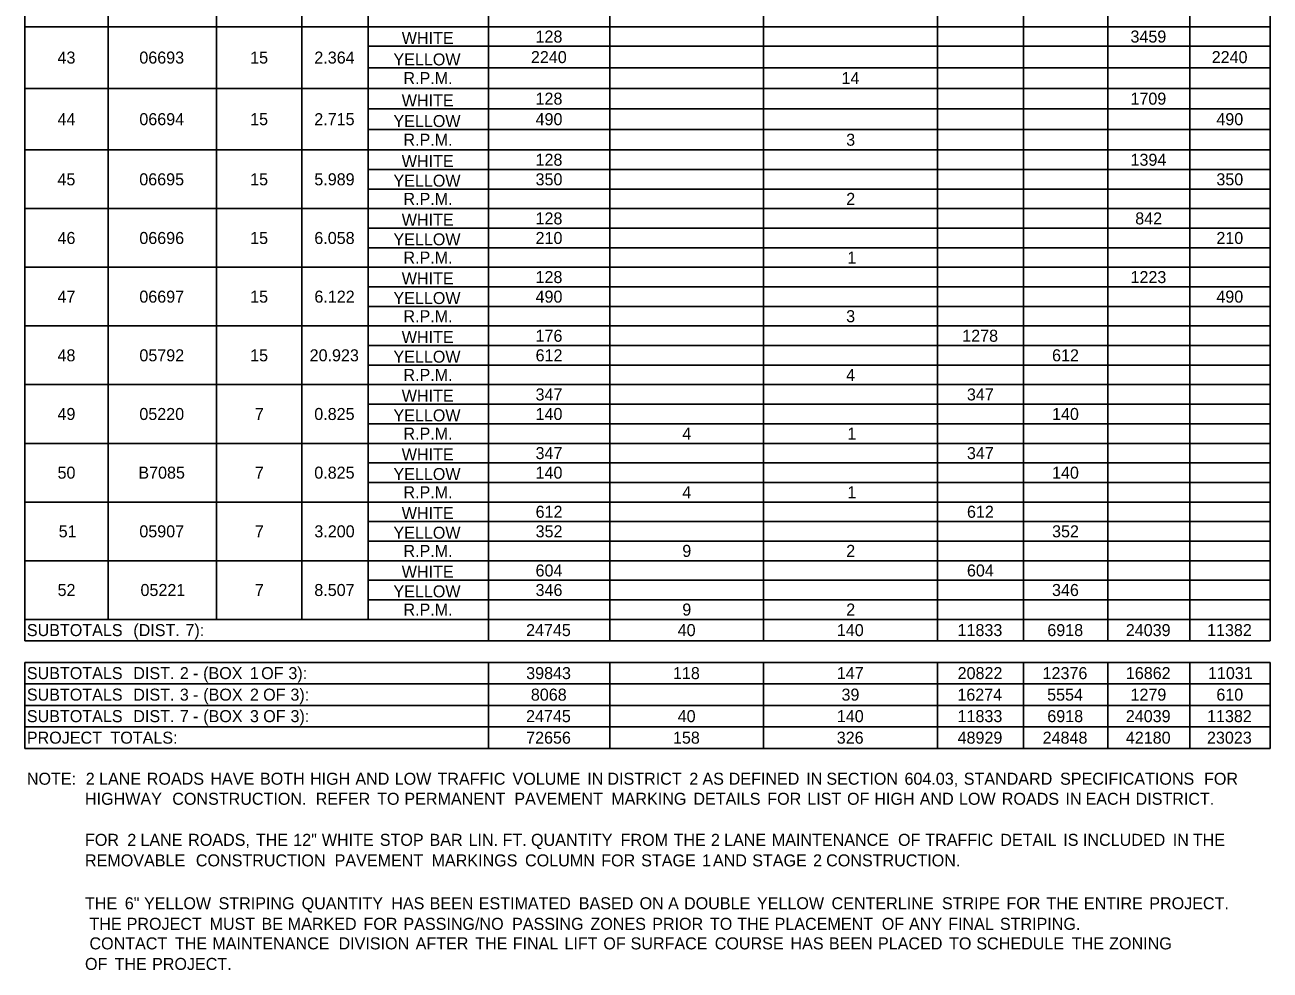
# Model space of a CAD drawing. Extents: x 544250 to 1930787, y -1948365 to 596640.
# Drawn here: x 551931 to 552552, y -1948306 to -1947835 of the extents above; entities that cross this region are included whole.
import ezdxf

# ---------------------------------------------------------------- set-up
doc = ezdxf.new("R2010")
doc.units = 0
doc.layers.add('Default', color=7, linetype='Continuous')

msp = doc.modelspace()

# ---------------------------------------------------------------- linework, layer by layer
at = {"layer": 'Default'}
for p, q in [((551930.97, -1948141.95), (551930.97, -1947372.68)), ((551972.4, -1948131.23), (551972.4, -1947372.68)), ((552026.52, -1948131.23), (552026.52, -1947372.68)), ((552068.93, -1948131.23), (552068.93, -1947372.68)), ((552102.08, -1948131.23), (552102.08, -1947372.68)), ((552162.04, -1948141.95), (552162.04, -1947372.68)), ((552385.8, -1948141.95), (552385.8, -1947372.68)), ((552470.63, -1948141.95), (552470.63, -1947372.68)), ((552551.55, -1948141.95), (552551.55, -1947372.68)), ((552026.52, -1948131.23), (552026.52, -1947440.93)), ((552068.93, -1948131.23), (552068.93, -1947440.93)), ((552222.49, -1948141.95), (552222.49, -1947440.93)), ((552299.03, -1948141.95), (552299.03, -1947440.93)), ((552428.7, -1948141.95), (552428.7, -1947440.93)), ((552511.58, -1948141.95), (552511.58, -1947440.93)), ((552470.63, -1947845.55), (552470.63, -1947826.05)), ((551930.97, -1947835.8), (552551.55, -1947835.8)), ((552162.04, -1947856.28), (552162.04, -1947835.8)), ((552385.8, -1947856.28), (552385.8, -1947835.8)), ((552102.08, -1947845.55), (552551.55, -1947845.55)), ((552511.58, -1947856.28), (552511.58, -1947845.55)), ((552102.08, -1947856.28), (552162.04, -1947856.28)), ((552102.08, -1947856.28), (552551.55, -1947856.28)), ((552470.63, -1947876.75), (552470.63, -1947856.28)), ((551930.97, -1947866.52), (552551.55, -1947866.52)), ((552162.04, -1947886.99), (552162.04, -1947866.52)), ((552385.8, -1947886.99), (552385.8, -1947866.52)), ((552102.08, -1947876.75), (552551.55, -1947876.75)), ((552511.58, -1947886.99), (552511.58, -1947876.75)), ((552102.08, -1947886.99), (552162.04, -1947886.99)), ((552102.08, -1947886.99), (552551.55, -1947886.99)), ((552470.63, -1947906.98), (552470.63, -1947886.99)), ((551930.97, -1947897.23), (552551.55, -1947897.23)), ((552162.04, -1947916.73), (552162.04, -1947897.23)), ((552385.8, -1947916.73), (552385.8, -1947897.23)), ((552102.08, -1947906.98), (552551.55, -1947906.98)), ((552511.58, -1947916.73), (552511.58, -1947906.98)), ((552102.08, -1947916.73), (552162.04, -1947916.73)), ((552102.08, -1947916.73), (552551.55, -1947916.73)), ((552470.63, -1947936.23), (552470.63, -1947916.73)), ((551930.97, -1947926.48), (552551.55, -1947926.48)), ((552162.04, -1947945.98), (552162.04, -1947926.48)), ((552385.8, -1947945.98), (552385.8, -1947926.48)), ((552102.08, -1947936.23), (552551.55, -1947936.23)), ((552511.58, -1947945.98), (552511.58, -1947936.23)), ((552102.08, -1947945.98), (552162.04, -1947945.98)), ((552102.08, -1947945.98), (552551.55, -1947945.98)), ((552470.63, -1947965.48), (552470.63, -1947945.98)), ((551930.97, -1947955.73), (552551.55, -1947955.73)), ((552162.04, -1947975.23), (552162.04, -1947955.73)), ((552385.8, -1947975.23), (552385.8, -1947955.73)), ((552102.08, -1947965.48), (552551.55, -1947965.48)), ((552511.58, -1947975.23), (552511.58, -1947965.48)), ((552102.08, -1947975.23), (552162.04, -1947975.23)), ((552102.08, -1947975.23), (552551.55, -1947975.23)), ((552470.63, -1947994.73), (552470.63, -1947975.23)), ((551930.97, -1947984.98), (552551.55, -1947984.98)), ((552102.08, -1947984.98), (552162.04, -1947984.98)), ((552102.08, -1948131.23), (552102.08, -1947984.98)), ((552162.04, -1948004.48), (552162.04, -1947984.98)), ((552385.8, -1948004.48), (552385.8, -1947984.98)), ((552102.08, -1947994.73), (552551.55, -1947994.73)), ((552511.58, -1948004.48), (552511.58, -1947994.73)), ((552102.08, -1948004.48), (552551.55, -1948004.48)), ((552470.63, -1948023.98), (552470.63, -1948004.48)), ((551930.97, -1948014.23), (552551.55, -1948014.23)), ((552102.08, -1948014.23), (552162.04, -1948014.23)), ((552162.04, -1948033.73), (552162.04, -1948014.23)), ((552385.8, -1948033.73), (552385.8, -1948014.23)), ((552102.08, -1948023.98), (552551.55, -1948023.98)), ((552511.58, -1948033.73), (552511.58, -1948023.98)), ((552102.08, -1948033.73), (552551.55, -1948033.73)), ((552470.63, -1948053.23), (552470.63, -1948033.73)), ((551930.97, -1948043.48), (552551.55, -1948043.48)), ((552102.08, -1948043.48), (552162.04, -1948043.48)), ((552162.04, -1948062.98), (552162.04, -1948043.48)), ((552385.8, -1948062.98), (552385.8, -1948043.48)), ((552102.08, -1948053.23), (552551.55, -1948053.23)), ((552511.58, -1948062.98), (552511.58, -1948053.23)), ((552102.08, -1948062.98), (552551.55, -1948062.98)), ((552470.63, -1948082.48), (552470.63, -1948062.98)), ((551930.97, -1948072.73), (552551.55, -1948072.73)), ((552102.08, -1948072.73), (552162.04, -1948072.73)), ((552162.04, -1948092.23), (552162.04, -1948072.73)), ((552385.8, -1948092.23), (552385.8, -1948072.73)), ((552102.08, -1948082.48), (552551.55, -1948082.48)), ((552511.58, -1948092.23), (552511.58, -1948082.48)), ((552102.08, -1948092.23), (552551.55, -1948092.23)), ((552470.63, -1948111.73), (552470.63, -1948092.23)), ((551930.97, -1948101.98), (552551.55, -1948101.98)), ((552102.08, -1948101.98), (552551.55, -1948101.98)), ((552162.04, -1948121.48), (552162.04, -1948101.98)), ((552385.8, -1948121.48), (552385.8, -1948101.98)), ((552102.08, -1948111.73), (552551.55, -1948111.73)), ((552511.58, -1948121.48), (552511.58, -1948111.73)), ((552102.08, -1948121.48), (552551.55, -1948121.48)), ((552470.63, -1948141.95), (552470.63, -1948121.48)), ((551930.97, -1948131.23), (552551.55, -1948131.23)), ((552162.04, -1948141.95), (552162.04, -1948131.23)), ((552222.49, -1948141.95), (552222.49, -1948131.23)), ((552299.03, -1948141.95), (552299.03, -1948131.23)), ((552385.8, -1948141.95), (552385.8, -1948131.23)), ((552428.7, -1948141.95), (552428.7, -1948131.23)), ((552511.58, -1948141.95), (552511.58, -1948131.23)), ((551930.97, -1948141.95), (552551.55, -1948141.95)), ((551930.97, -1948152.68), (552551.55, -1948152.68)), ((551930.97, -1948152.68), (552551.55, -1948152.68)), ((551930.97, -1948195.58), (551930.97, -1948152.68)), ((552162.04, -1948195.58), (552162.04, -1948152.68)), ((552162.04, -1948195.58), (552162.04, -1948152.68)), ((552222.49, -1948195.58), (552222.49, -1948152.68)), ((552299.03, -1948195.58), (552299.03, -1948152.68)), ((552385.8, -1948195.58), (552385.8, -1948152.68)), ((552428.7, -1948195.58), (552428.7, -1948152.68)), ((552470.63, -1948195.58), (552470.63, -1948152.68)), ((552511.58, -1948195.58), (552511.58, -1948152.68)), ((552551.55, -1948195.58), (552551.55, -1948152.68)), ((551930.97, -1948163.4), (552551.55, -1948163.4)), ((551930.97, -1948174.13), (552551.55, -1948174.13)), ((551930.97, -1948184.85), (552551.55, -1948184.85)), ((551930.97, -1948195.58), (552551.55, -1948195.58))]:
    msp.add_line(p, q, dxfattribs=at)

# ---------------------------------------------------------------- texts
for s, p in [('128', (552185.46, -1947843.68)), ('3459', (552481.97, -1947843.68)), ('WHITE', (552118.78, -1947844.35)), ('43', (551947.22, -1947854.16)), ('06693', (551988, -1947854.16)), ('15', (552043.23, -1947854.16)), ('2.364', (552075.22, -1947854.16)), ('YELLOW', (552114.64, -1947855.08)), ('2240', (552183.15, -1947853.92)), ('2240', (552522.45, -1947853.92)), ('R.P.M.', (552119.62, -1947864.4)), ('14', (552337.96, -1947864.4)), ('128', (552185.46, -1947874.64)), ('1709', (552481.97, -1947874.64)), ('WHITE', (552118.78, -1947875.55)), ('44', (551947.23, -1947884.87)), ('06694', (551988.01, -1947884.87)), ('15', (552043.23, -1947884.87)), ('2.715', (552075.19, -1947884.87)), ('YELLOW', (552114.64, -1947885.79)), ('490', (552185.48, -1947884.87)), ('490', (552524.78, -1947884.87)), ('R.P.M.', (552119.62, -1947895.11)), ('3', (552340.28, -1947895.11)), ('WHITE', (552118.78, -1947905.78)), ('128', (552185.46, -1947905.1)), ('1394', (552481.99, -1947905.1)), ('45', (551947.19, -1947914.85)), ('06695', (551987.98, -1947914.85)), ('15', (552043.23, -1947914.85)), ('5.989', (552075.21, -1947914.85)), ('YELLOW', (552114.64, -1947915.53)), ('350', (552185.48, -1947914.85)), ('350', (552524.78, -1947914.85)), ('R.P.M.', (552119.62, -1947924.6)), ('2', (552340.31, -1947924.6)), ('WHITE', (552118.78, -1947935.03)), ('128', (552185.46, -1947934.35)), ('842', (552484.34, -1947934.35)), ('46', (551947.22, -1947944.1)), ('06696', (551988, -1947944.1)), ('15', (552043.23, -1947944.1)), ('6.058', (552075.21, -1947944.1)), ('YELLOW', (552114.64, -1947944.78)), ('210', (552185.48, -1947944.1)), ('210', (552524.78, -1947944.1)), ('R.P.M.', (552119.62, -1947953.85)), ('1', (552340.86, -1947953.85)), ('WHITE', (552118.78, -1947964.28)), ('128', (552185.46, -1947963.6)), ('1223', (552481.97, -1947963.6)), ('47', (551947.22, -1947973.35)), ('06697', (551988, -1947973.35)), ('15', (552043.23, -1947973.35)), ('6.122', (552075.24, -1947973.35)), ('YELLOW', (552114.64, -1947974.03)), ('490', (552185.48, -1947973.35)), ('490', (552524.78, -1947973.35)), ('R.P.M.', (552119.62, -1947983.1)), ('3', (552340.28, -1947983.1)), ('176', (552185.47, -1947992.85)), ('1278', (552398.12, -1947992.85)), ('WHITE', (552118.78, -1947993.53)), ('48', (551947.21, -1948002.6)), ('05792', (551988.03, -1948002.6)), ('15', (552043.23, -1948002.6)), ('20.923', (552072.88, -1948002.6)), ('YELLOW', (552114.64, -1948003.28)), ('612', (552185.5, -1948002.6)), ('612', (552442.9, -1948002.6)), ('R.P.M.', (552119.62, -1948012.35)), ('4', (552340.29, -1948012.35)), ('WHITE', (552118.78, -1948022.78)), ('347', (552185.47, -1948022.1)), ('347', (552400.45, -1948022.1)), ('49', (551947.21, -1948031.85)), ('05220', (551988.01, -1948031.85)), ('7', (552045.58, -1948031.85)), ('0.825', (552075.19, -1948031.85)), ('YELLOW', (552114.64, -1948032.53)), ('140', (552185.48, -1948031.85)), ('140', (552442.88, -1948031.85)), ('R.P.M.', (552119.62, -1948041.6)), ('4', (552258.63, -1948041.6)), ('1', (552340.86, -1948041.6)), ('WHITE', (552118.78, -1948052.03)), ('347', (552185.47, -1948051.35)), ('347', (552400.45, -1948051.35)), ('50', (551947.23, -1948061.1)), ('B7085', (551987.51, -1948061.1)), ('7', (552045.58, -1948061.1)), ('0.825', (552075.19, -1948061.1)), ('140', (552185.48, -1948061.1)), ('140', (552442.88, -1948061.1)), ('YELLOW', (552114.64, -1948061.78)), ('R.P.M.', (552119.62, -1948070.85)), ('4', (552258.63, -1948070.85)), ('1', (552340.86, -1948070.85)), ('WHITE', (552118.78, -1948081.28)), ('612', (552185.5, -1948080.6)), ('612', (552400.49, -1948080.6)), ('51', (551947.8, -1948090.35)), ('05907', (551988, -1948090.35)), ('7', (552045.58, -1948090.35)), ('3.200', (552075.22, -1948090.35)), ('YELLOW', (552114.64, -1948091.03)), ('352', (552185.5, -1948090.35)), ('352', (552442.9, -1948090.35)), ('R.P.M.', (552119.62, -1948100.1)), ('9', (552258.62, -1948100.1)), ('2', (552340.31, -1948100.1)), ('WHITE', (552118.78, -1948110.53)), ('604', (552185.48, -1948109.85)), ('604', (552400.47, -1948109.85)), ('52', (551947.25, -1948119.6)), ('05221', (551988.58, -1948119.6)), ('7', (552045.58, -1948119.6)), ('8.507', (552075.21, -1948119.6)), ('YELLOW', (552114.64, -1948120.28)), ('346', (552185.47, -1948119.6)), ('346', (552442.87, -1948119.6)), ('R.P.M.', (552119.62, -1948129.35)), ('9', (552258.62, -1948129.35)), ('2', (552340.31, -1948129.35)), ('SUBTOTALS', (551931.94, -1948139.59)), (' (DIST.', (551982.77, -1948139.59)), (' 7):', (552008.73, -1948139.59)), ('24745', (552180.74, -1948139.59)), ('40', (552256.31, -1948139.59)), ('140', (552335.63, -1948139.59)), ('11833', (552395.79, -1948139.59)), ('6918', (552440.53, -1948139.59)), ('24039', (552479.65, -1948139.59)), ('11382', (552520.13, -1948139.59)), ('SUBTOTALS', (551931.94, -1948161.04)), (' DIST.', (551982.77, -1948161.04)), (' 2', (552005.95, -1948161.04)), (' -', (552012.51, -1948161.04)), (' (BOX', (552017.57, -1948161.04)), (' 1', (552040.85, -1948161.04)), (' OF', (552046.48, -1948161.04)), (' 3):', (552060.06, -1948161.04)), ('39843', (552180.8, -1948161.04)), ('118', (552253.96, -1948161.04)), ('147', (552335.61, -1948161.04)), ('20822', (552395.82, -1948161.04)), ('12376', (552438.17, -1948161.04)), ('16862', (552479.67, -1948161.04)), ('11031', (552520.6, -1948161.04)), ('SUBTOTALS', (551931.94, -1948171.77)), (' DIST.', (551982.77, -1948171.77)), (' 3', (552005.95, -1948171.77)), (' (BOX', (552017.63, -1948171.77)), (' 2', (552040.91, -1948171.77)), (' OF', (552047.47, -1948171.77)), (' 3):', (552061.06, -1948171.77)), ('8068', (552183.13, -1948171.77)), ('39', (552337.95, -1948171.77)), ('16274', (552395.7, -1948171.77)), ('5554', (552440.44, -1948171.77)), ('1279', (552481.98, -1948171.77)), ('610', (552524.78, -1948171.77)), (' -', (552012.57, -1948171.77)), ('SUBTOTALS', (551931.94, -1948182.49)), (' DIST.', (551982.77, -1948182.49)), (' 7', (552005.95, -1948182.49)), (' (BOX', (552017.62, -1948182.49)), (' 3', (552040.9, -1948182.49)), (' OF', (552047.52, -1948182.49)), (' 3):', (552061.11, -1948182.49)), ('24745', (552180.74, -1948182.49)), ('40', (552256.31, -1948182.49)), ('140', (552335.63, -1948182.49)), ('11833', (552395.79, -1948182.49)), ('6918', (552440.53, -1948182.49)), ('24039', (552479.65, -1948182.49)), ('11382', (552520.13, -1948182.49)), (' -', (552012.56, -1948182.49)), ('PROJECT', (551931.94, -1948193.22)), (' TOTALS:', (551971.37, -1948193.22)), ('72656', (552180.77, -1948193.22)), ('158', (552253.96, -1948193.22)), ('326', (552335.58, -1948193.22)), ('48929', (552395.8, -1948193.22)), ('24848', (552438.2, -1948193.22)), ('42180', (552479.66, -1948193.22)), ('23023', (552520.1, -1948193.22)), ('NOTE:', (551931.94, -1948213.69)), ('  2', (551956.83, -1948213.69)), (' LANE', (551965.7, -1948213.69)), (' ROADS', (551989.48, -1948213.69)), (' HAVE', (552021.19, -1948213.69)), (' BOTH', (552045.9, -1948213.69)), (' HIGH', (552070.84, -1948213.69)), (' AND', (552093.45, -1948213.69)), (' LOW', (552113.04, -1948213.69)), (' TRAFFIC', (552134.36, -1948213.69)), (' VOLUME', (552171.75, -1948213.69)), (' IN', (552209.04, -1948213.69)), (' DISTRICT', (552219.06, -1948213.69)), (' 2', (552259.88, -1948213.69)), (' AS', (552266.42, -1948213.69)), (' DEFINED', (552279.49, -1948213.69)), (' IN', (552318.17, -1948213.69)), (' SECTION', (552328.2, -1948213.69)), (' 604.03,', (552367.11, -1948213.69)), (' STANDARD', (552396.65, -1948213.69)), (' SPECIFICATIONS', (552444.65, -1948213.69)), (' FOR', (552516.41, -1948213.69)), ('             HIGHWAY', (551931.94, -1948223.69)), (' CONSTRUCTION.', (552002.2, -1948223.69)), (' REFER', (552073.66, -1948223.69)), (' TO', (552104.29, -1948223.69)), (' PERMANENT', (552117.88, -1948223.69)), (' PAVEMENT', (552172.68, -1948223.69)), (' MARKING', (552220.97, -1948223.69)), (' DETAILS', (552261.9, -1948223.69)), (' FOR', (552298.73, -1948223.69)), (' LIST', (552318.64, -1948223.69)), (' OF', (552338.5, -1948223.69)), (' HIGH', (552352.09, -1948223.69)), (' AND', (552374.7, -1948223.69)), (' LOW', (552394.28, -1948223.69)), (' ROADS', (552415.61, -1948223.69)), (' IN', (552447.31, -1948223.69)), (' EACH', (552457.34, -1948223.69)), (' DISTRICT.', (552482.28, -1948223.69)), ('             FOR', (551931.94, -1948244.16)), (' 2', (551979.79, -1948244.16)), (' LANE', (551986.33, -1948244.16)), (' ROADS,', (552010.11, -1948244.16)), (' THE', (552043.84, -1948244.16)), (' 12"', (552062.49, -1948244.16)), (' WHITE', (552076.72, -1948244.16)), (' STOP', (552105.61, -1948244.16)), (' BAR', (552130.4, -1948244.16)), (' LIN.', (552149.85, -1948244.16)), (' FT.', (552166.82, -1948244.16)), (' QUANTITY', (552180.99, -1948244.16)), (' FROM', (552225.64, -1948244.16)), (' THE', (552252.02, -1948244.16)), (' 2', (552270.67, -1948244.16)), (' LANE', (552277.21, -1948244.16)), (' MAINTENANCE', (552300.99, -1948244.16)), (' OF', (552363.9, -1948244.16)), (' TRAFFIC', (552377.48, -1948244.16)), (' DETAIL', (552414.87, -1948244.16)), (' IS', (552446.25, -1948244.16)), (' INCLUDED', (552456.06, -1948244.16)), (' IN', (552500.8, -1948244.16)), (' THE', (552510.82, -1948244.16)), ('             REMOVABLE', (551931.94, -1948254.4)), (' CONSTRUCTION', (552013.94, -1948254.4)), (' PAVEMENT', (552083.12, -1948254.4)), (' MARKINGS', (552131.4, -1948254.4)), (' COLUMN', (552178.01, -1948254.4)), (' FOR', (552215.98, -1948254.4)), (' STAGE', (552235.89, -1948254.4)), (' 1', (552266.2, -1948254.4)), (' AND', (552271.64, -1948254.4)), (' STAGE', (552291.22, -1948254.4)), (' 2', (552321.53, -1948254.4)), (' CONSTRUCTION.', (552328.07, -1948254.4)), ('             THE', (551931.94, -1948275.79)), (' 6"', (551978.52, -1948275.79)), (' YELLOW', (551988.1, -1948275.79)), (' STRIPING', (552025.27, -1948275.79)), (' QUANTITY', (552066.66, -1948275.79)), (' HAS', (552111.32, -1948275.79)), (' BEEN', (552130.45, -1948275.79)), (' ESTIMATED', (552154.92, -1948275.79)), (' BASED', (552204.78, -1948275.79)), (' ON', (552235.09, -1948275.79)), (' A', (552249.31, -1948275.79)), (' DOUBLE', (552257.24, -1948275.79)), (' YELLOW', (552293.6, -1948275.79)), (' CENTERLINE', (552330.77, -1948275.79)), (' STRIPE', (552385.76, -1948275.79)), (' FOR', (552417.92, -1948275.79)), (' THE', (552437.83, -1948275.79)), (' ENTIRE', (552456.48, -1948275.79)), (' PROJECT.', (552489.11, -1948275.79)), ('THE', (551963.14, -1948286.03)), (' PROJECT', (551979.46, -1948286.03)), (' MUST', (552020.76, -1948286.03)), (' BE', (552046.67, -1948286.03)), (' MARKED', (552059.73, -1948286.03)), (' FOR', (552097.48, -1948286.03)), (' PASSING/NO', (552117.4, -1948286.03)), (' PASSING', (552171.53, -1948286.03)), (' ZONES', (552210.61, -1948286.03)), (' PRIOR', (552241.38, -1948286.03)), (' TO', (552270.14, -1948286.03)), (' THE', (552283.74, -1948286.03)), (' PLACEMENT', (552302.39, -1948286.03)), (' OF', (552355.79, -1948286.03)), (' ANY', (552369.38, -1948286.03)), (' FINAL', (552388.89, -1948286.03)), (' STRIPING.', (552414.67, -1948286.03)), ('CONTACT', (551963.14, -1948295.78)), (' THE', (552003.5, -1948295.78)), (' MAINTENANCE', (552022.15, -1948295.78)), (' DIVISION', (552085.05, -1948295.78)), (' AFTER', (552123.49, -1948295.78)), (' THE', (552153.19, -1948295.78)), (' FINAL', (552171.84, -1948295.78)), (' LIFT', (552197.63, -1948295.78)), (' OF', (552217.02, -1948295.78)), (' SURFACE', (552230.6, -1948295.78)), (' COURSE', (552272.55, -1948295.78)), (' HAS', (552310.3, -1948295.78)), (' BEEN', (552329.43, -1948295.78)), (' PLACED', (552353.91, -1948295.78)), (' TO', (552389.33, -1948295.78)), (' SCHEDULE', (552402.93, -1948295.78)), (' THE', (552450.47, -1948295.78)), (' ZONING', (552469.12, -1948295.78)), ('             OF', (551931.94, -1948306.02)), (' THE', (551973.46, -1948306.02)), (' PROJECT.', (551992.11, -1948306.02))]:
    msp.add_text(s, height=6, dxfattribs=at).set_placement(p)

doc.saveas('drawing.dxf')
